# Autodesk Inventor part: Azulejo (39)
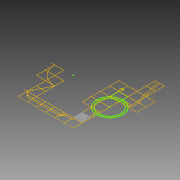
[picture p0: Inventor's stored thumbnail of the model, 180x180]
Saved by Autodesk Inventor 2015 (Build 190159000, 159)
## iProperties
Created: 2015-04
Part Number: Azulejo (39)
Material: Genérico
Document SubType Name: Modeling
Designer: Felipe
Density: 1 g/cm^3
Appearance: Padrão
Author: Felipe
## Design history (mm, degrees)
sketch "Sketch1"
  geometry: L1 (-1510, -7490)-(-1510, -6010); L2 (-3010, -1490)-(-3010, -10); L3 (-2990, 10)-(-1510, 10); L4 (-1510, -10)-(-2990, -10); L5 (-1510, -1490)-(-1510, -10); L6 (-1490, -10)-(-1490, -1490); L7 (-1490, -1490)-(-10, -1490); L8 (-10, -1510)-(-1490, -1510); L9 (-10, -2990)-(-10, -1510); L10 (-10, -5990)-(-10, -4510); L11 (-1490, -7490)-(-10, -7490); L12 (4490, -6010)-(3010, -6010); L13 (10, -1510)-(10, -2990); L14 (10, -3010)-(10, -4490); L15 (10, -4510)-(10, -5990); L16 (10, -5990)-(1490, -5990); L17 (1490, -6010)-(10, -6010); L18 (10, -7490)-(1490, -7490); L19 (1510, -5990)-(2990, -5990); L20 (2990, -6010)-(1510, -6010); L21 (1510, -7490)-(2990, -7490); L22 (4490, 1510)-(4490, 2990); L23 (4490, 10)-(4490, 1490); L24 (4490, -1490)-(4490, -10); L25 (4490, -2990)-(4490, -1510); L26 (3010, -5990)-(4490, -5990); L27 (3010, -7490)-(4490, -7490); L28 (4510, 3010)-(5990, 3010); L29 (5990, 2990)-(4510, 2990); L30 (4510, 2990)-(4510, 1510); L31 (4510, 1510)-(5990, 1510); L32 (5990, 1510)-(5990, 1740.185); L33 (5990, 1760.2)-(5990, 2259.8); L34 (5990, 2279.815)-(5990, 2990); L35 (5990, 1490)-(4510, 1490); L36 (4510, 1490)-(4510, 10); L37 (4510, 10)-(5990, 10); L38 (5990, 10)-(5990, 1490); L39 (5975.983, -10)-(4510, -10); L40 (4510, -10)-(4510, -1490); L41 (5990, -1510)-(5782.897, -1510); L42 (5782.897, -1510)-(5688.66, -1510); L43 (5668.66, -1510)-(5482.895, -1510); L44 (5482.895, -1510)-(5388.656, -1510); L45 (5368.656, -1510)-(4510, -1510); L46 (4510, -1510)-(4510, -2990); L47 (4510, -2990)-(5975.983, -2990); L48 (5990, -2975.728)-(5990, -2837.377); L49 (5990, -2837.377)-(5990, -2536.247); L50 (5990, -2500.476)-(5990, -2317.632); L51 (5990, -2317.632)-(5990, -1510); L52 (5990, -3010)-(4510, -3010); L53 (5990, -4490)-(5990, -3010); L54 (4510, -5990)-(5990, -5990); L55 (5990, -5990)-(5990, -4510); L56 (4510, -7490)-(5990, -7490); L57 (5990, -7490)-(5990, -6310); L58 (5990, -6290)-(5990, -6010); L59 (7490, 4510)-(7490, 5990); L60 (6010, 3010)-(7490, 3010); L61 (7490, 3010)-(7490, 4490); L62 (7490, 2990)-(6010, 2990); L63 (6010, 2990)-(6010, 2279.815); L64 (6010, 2259.8)-(6010, 1760.2)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; A1 r 250 centre (6000, 2010) between (5990, 2259.8) and (5990, 1760.2); A2 r 250 centre (6000, 2010) between (6010, 1760.2) and (6010, 2259.8); A3 r 270 centre (6000, 2010) between (5990, 2279.815) and (5990, 1740.185); A4 r 270 centre (6000, 2010) between (6010, 1740.185) and (6010, 2279.815); A5 r 3010.017 centre (0, 0) between (-1490, -2615.358) and (-346.554, -2990); A6 r 2990.017 centre (0, 0) between (-1490, -2592.316) and (-10, -2990); A7 r 3010.017 centre (0, 0) between (-2603.863, -1510) and (-1510, -2603.863); A8 r 2990.017 centre (0, 0) between (-2580.717, -1510) and (-1510, -2580.717); A9 r 3010.017 centre (0, 0) between (-2990, -346.554) and (-2615.358, -1490); A10 r 2990.017 centre (0, 0) between (-2990, -10) and (-2592.316, -1490); A11 r 2131.367 centre (7500, -1500) between (7490, 631.344) and (6010, 24.017); A12 r 2131.367 centre (7500, -1500) between (5975.983, -10) and (5368.656, -1490); A13 r 2131.367 centre (7500, -1500) between (5368.656, -1510) and (5975.983, -2990); A14 r 2131.367 centre (7500, -1500) between (6010, -3024.017) and (7190, -3608.703); A15 r 1831.367 centre (7500, -1500) between (7490.321, 331.342) and (6463.753, 10); A16 r 1831.367 centre (7500, -1500) between (7489.976, 331.34) and (6010, -435.196); A17 r 1831.367 centre (7500, -1500) between (5990, -463.753) and (5668.66, -1490); A18 r 1831.367 centre (7500, -1500) between (5668.66, -1510) and (5990, -2536.247); A19 r 1831.367 centre (7500, -1500) between (6010, -2564.804) and (6435.196, -2990); A20 r 1831.367 centre (7500, -1500) between (6463.753, -3010) and (7490, -3331.34); A21 r 2111.367 centre (7500, -1500) between (7490.389, 611.346) and (6024.272, 10); A22 r 2111.367 centre (7500, -1500) between (5990, -24.272) and (5388.656, -1490); A23 r 2111.367 centre (7500, -1500) between (5388.656, -1510) and (5990, -2975.728); A24 r 2111.367 centre (7500, -1500) between (6024.272, -3010) and (7210, -3591.357); A25 r 1811.367 centre (7499.986, -1499.91) between (7490.524, 311.432) and (6499.51, 10.09); A26 r 1811.367 centre (7500, -1500) between (6469.975, -10) and (6010, -469.975); A27 r 1811.367 centre (7500, -1500) between (5990, -499.524) and (5688.66, -1490); A28 r 1811.367 centre (7500, -1500) between (5688.66, -1510) and (5990, -2500.476); A29 r 1811.367 centre (7500, -1500) between (6010, -2530.025) and (6469.975, -2990); A30 r 1811.367 centre (7500, -1500) between (6499.524, -3010) and (7490, -3311.34); A31 r 449.871 centre (7499.449, -4060.672) between (7510, -4510.419) and (7521.546, -4510); A32 r 2111.367 centre (7500, -1500) between (7490.019, 611.344) and (7490.389, 611.346); A33 r 1831.367 centre (7500, -1500) between (7489.976, 331.34) and (7490.321, 331.342); A34 r 1811.367 centre (7499.986, -1499.91) between (7489.986, 311.429) and (7490.524, 311.432); A35 r 2131.367 centre (7500, -1500) between (7510, -3631.344) and (7190, -3608.703); A36 r 2131.367 centre (7500, -1500) between (7210, -3611.546) and (7490, -3631.344); 12 further points
  constraints: 718 end point, 82 point on circle, 36 centre point, 14 point on line, 3 concentric, 2 parallel, 2 perpendicular, 1 collinear, 1 horizontal, 1 vertical, 1 other
extrude "Extrusion1" new body sketch "Sketch1" distance "d0" = 60; taper "d1" = 0 deg
extrude "Extrusion2" new body sketch "Sketch1" distance "d2" = 60; taper "d3" = 0 deg
extrude "Extrusion3" new body sketch "Sketch1" distance "d4" = 60; taper "d5" = 0 deg
body "Solid1"
body "Solid2"
body "Solid3"
